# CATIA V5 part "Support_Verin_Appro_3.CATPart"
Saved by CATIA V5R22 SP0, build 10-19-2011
Part number: Support_Verin_Flacon_AV
Bounding box of the stored display mesh (mm): x -18.5 to 18.5, y -24 to 0, z -20 to 18.312
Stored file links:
  U:\S9A\PER\CAO\Assemblage\Reservoir_Flacon\Verin\Poussoir_2\Support_Verin_Appro_3.CATPart
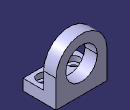
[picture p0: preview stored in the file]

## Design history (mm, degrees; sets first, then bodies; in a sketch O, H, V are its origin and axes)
Body1 (main body)
  Sketch1 on zx-plane, origin (0, 0, 0), H (-1, 0, 0), V (0, 0, 1)
    circle A1 centre (0, 0) radius 11.5
    arc A2 centre (0, 0) radius 18.5 from (18.5, 0) to (-18.5, 0) ccw
    line L1 (18.5, -20) -> (-18.5, -20)
    line L2 (-18.5, -20) -> (-18.5, 0)
    line L3 (18.5, 0) -> (18.5, -20)
    radius A1 = 11.5
    distance A2 A1 = 7
    length L2 = 20
    distance L1 H = 20
    horizontal: L1 H
    vertical: L2 V, L3 V
    tangency: L3 A2
  Pad1: profile Sketch1, direction (0, -1, 0), length 9
  Sketch2 on end face of Pad1, origin (0, -9, 0), H (1, 0, 0), V (0, 0, 1)
    point P1 (18.5, -20)
    line L1 (18.5, -20) -> (-18.5, -20)
    line L2 (-18.5, -20) -> (-18.5, -12)
    line L3 (-18.5, -12) -> (18.5, -12)
    line L4 (18.5, -12) -> (18.5, -20)
    point P2 (-18.5, -20)
    reference projected point E1 (18.5, -20) from vertex [face of Pad1 from Sketch1.L1 | end face of Pad1 | face of Pad1 from Sketch1.L2]
    reference projected point E2 (-18.5, -20) from vertex [face of Pad1 from Sketch1.L3 | end face of Pad1 | face of Pad1 from Sketch1.L1]
    distance L3 H = 12
    horizontal: L1 H, L3 H
    vertical: L2 V, L4 V
    coincidence: P1 E1, E2 P2
  Pad2: profile Sketch2, direction (0, -1, 0), length 15
  Sketch3 on face of Pad2 from Sketch2.L3, origin (5.7564, -18.4322, -12), H (1, 0, 0), V (0, 1, 0)
    point P1 (4.7436, 1.9322)
    reference projected line E1 (12.7436, -5.5678) -> (-24.2564, -5.5678) from edge [face of Pad2 from Sketch2.L3 | end face of Pad2]
    reference projected line E2 (-24.2564, 9.4322) -> (12.7436, 9.4322) from edge [end face of Pad1 | face of Pad1 from Sketch1.A2]
    reference projected line E3 (12.7436, 9.4322) -> (12.7436, -5.5678) from edge [face of Pad2 from Sketch2.L3 | face of Pad2]
    distance P1 E3 = 8
    equidistance: E1 E2 P1
  Hole1: placed by Sketch3, at (10.5, -16.5, -12) direction (0, 0, -1), diameter 5, through (limit type 6), counterbore diameter 10, counterbore depth 4
  Mirror1: of Hole1, about yz-plane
